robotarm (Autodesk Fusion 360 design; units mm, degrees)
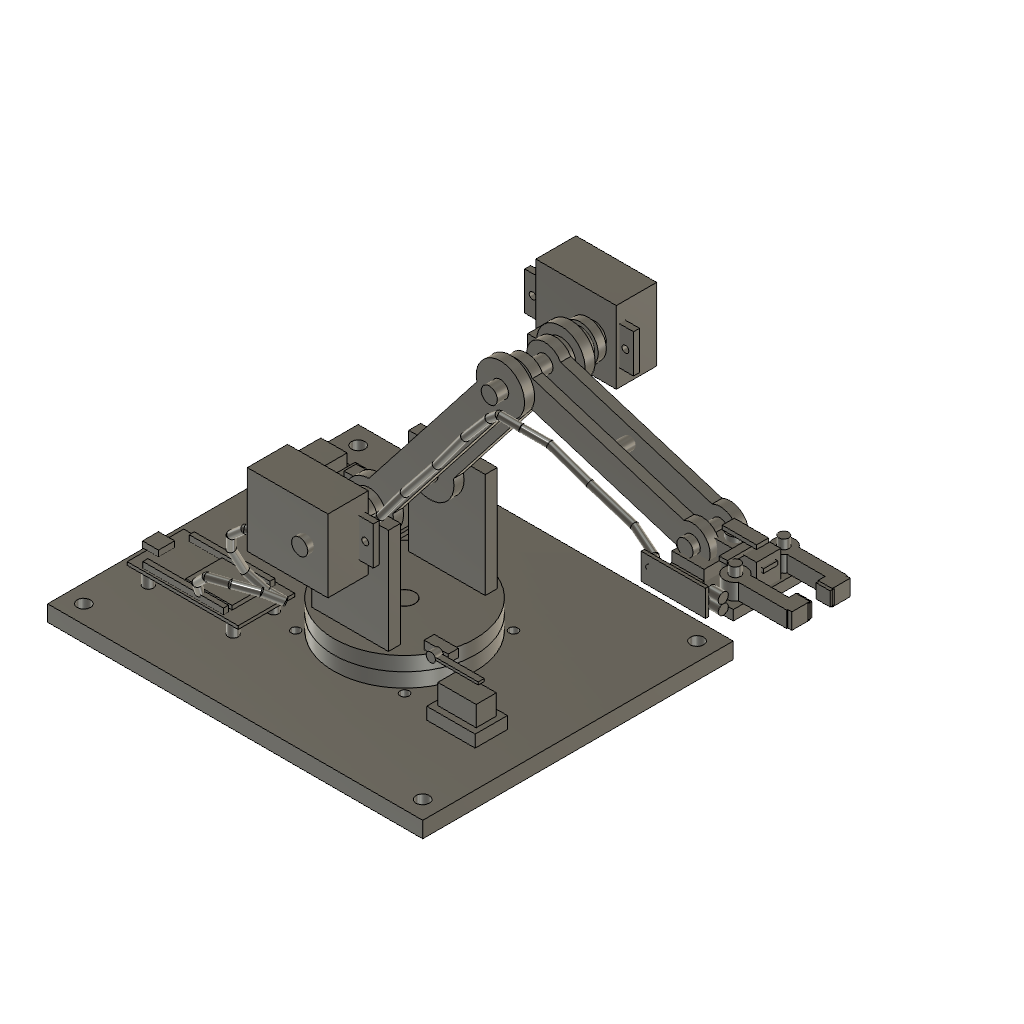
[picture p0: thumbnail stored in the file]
part number: 2026-11-24-23-50-12-086
part number: 2026-11-24-23-50-12-224
part number: 2026-11-24-23-50-12-256
part number: 2026-11-24-23-50-12-289
part number: 2026-11-24-23-50-12-323
part number: 2026-11-24-23-50-12-349
part number: 2026-11-24-23-50-12-379
part number: 2026-11-24-23-50-12-404
part number: 2026-11-24-23-50-12-427
part number: 2026-11-24-23-50-12-457
part number: 2026-11-24-23-50-12-485
part number: 2026-11-24-23-50-12-512
base_feature "Base Feature1" bodies "Base plate with corner and bearing holes", "Bearing lower race", "Turntable actuator envelope", "Turntable output shaft"
base_feature "Base Feature1" bodies "Turntable top plate", "Shoulder clevis cheek", "Shoulder clevis cheek (1)", "Servo housing envelope", "Mounting flange with M3 clearance", "Output boss", "Horn and shaft", "Shoulder servo mounting bridge"
base_feature "Base Feature1" bodies "Left shoulder link, 105 mm pivot spacing", "Right shoulder link, 105 mm pivot spacing", "Shoulder drive coupling", "Elbow servo mounting bridge", "Upper link cross spacer", "Elbow support pin", "Servo housing envelope", "Mounting flange with M3 clearance"
base_feature "Base Feature1" bodies "Left forearm link, 91 mm pivot spacing", "Right forearm link, 91 mm pivot spacing", "Forearm cross spacer", "Elbow drive coupling", "Wrist spacer and bolt pin", "Fixed wrist tool plate"
base_feature "Base Feature1" bodies "Tool carrier", "Micro servo package", "Servo output", "Servo horn", "Opposite jaw pivot", "Driven jaw pivot", "Drive link", "Synchronizer mounting envelope"
base_feature "Base Feature1" bodies "Jaw with pivot bore", "Grip pad"
base_feature "Base Feature1" bodies "Jaw with pivot bore", "Grip pad"
base_feature "Base Feature1" bodies "ESP32 board envelope", "Module shield", "Accessible USB connector", "GPIO header A", "GPIO header B", "PCB standoff", "PCB standoff (1)", "PCB standoff (2)"
base_feature "Base Feature1" bodies "Power board envelope", "External supply terminal block", "Servo power terminal block", "Power switch housing", "Switch actuator", "Power tray support"
base_feature "Base Feature1" bodies "Home switch mounting bracket", "Switch body", "Roller lever", "Lever roller"
base_feature "Base Feature1" bodies "Sensor mount", "IR module board envelope", "IR emitter", "IR receiver"
base_feature "Base Feature2" bodies "Wire retention clip"
base_feature "Base Feature2" bodies "Wire retention clip"
base_feature "Base Feature2" bodies "Wire retention clip"
base_feature "Base Feature2" bodies "Cable 1 - board to turntable"
base_feature "Base Feature3" bodies "Cable 2 - slack loop to shoulder servo"
base_feature "Base Feature3" bodies "Cable 3 - harness along upper arm"
base_feature "Base Feature3" bodies "Cable 4 - forearm to wrist IR sensor"
ground "Pin"
sketch "J1 Base yaw pivot reference" plane through (0, 0, 0) normal (0, 0, 1) x axis (1, 0, 0)
as_built_joint "As-built1" RotateMinimum -70 RotateMaximum 70
sketch "J2 Shoulder pitch pivot reference" plane through (0, 0, 0) normal (0, 0, 1) x axis (1, 0, 0)
as_built_joint "As-built2" RotateMinimum -30 RotateMaximum 35
sketch "J3 Elbow pitch pivot reference" plane through (0, 0, 0) normal (0, 0, 1) x axis (1, 0, 0)
as_built_joint "As-built3" RotateMinimum -35 RotateMaximum 40
sketch "J4 Driven jaw pivot reference" plane through (0, 0, 0) normal (0, 0, 1) x axis (1, 0, 0)
as_built_joint "As-built4" RotateMinimum -12 RotateMaximum 8
sketch "Follower jaw pivot pivot reference" plane through (0, 0, 0) normal (0, 0, 1) x axis (1, 0, 0)
as_built_joint "As-built5" RotateMinimum -8 RotateMaximum 12
as_built_joint "As-built6"
as_built_joint "As-built7"
as_built_joint "As-built8"
as_built_joint "As-built9"
as_built_joint "As-built10"
motion_link "MotionLink1" Value1 1 Value2 1
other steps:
create_component "CreateComponent1"
create_component "CreateComponent2"
create_component "CreateComponent3"
create_component "CreateComponent4"
create_component "CreateComponent5"
create_component "CreateComponent6"
create_component "CreateComponent7"
create_component "CreateComponent8"
create_component "CreateComponent9"
create_component "CreateComponent10"
create_component "CreateComponent11"
named bodies: "Base plate with corner and bearing holes", "Bearing lower race", "Turntable actuator envelope", "Turntable output shaft", "Turntable top plate", "Shoulder clevis cheek", "Shoulder clevis cheek (1)", "Servo housing envelope", "Mounting flange with M3 clearance", "Output boss", "Horn and shaft", "Shoulder servo mounting bridge", "Shoulder support pin", "Home flag carrier", "Left shoulder link, 105 mm pivot spacing", "Right shoulder link, 105 mm pivot spacing", "Shoulder drive coupling", "Elbow servo mounting bridge", "Upper link cross spacer", "Elbow support pin", "Left forearm link, 91 mm pivot spacing", "Right forearm link, 91 mm pivot spacing", "Forearm cross spacer", "Elbow drive coupling", "Wrist spacer and bolt pin", "Fixed wrist tool plate", "Tool carrier", "Micro servo package", "Servo output", "Servo horn", "Opposite jaw pivot", "Driven jaw pivot", "Drive link", "Synchronizer mounting envelope", "Jaw with pivot bore", "Grip pad", "ESP32 board envelope", "Module shield", "Accessible USB connector", "GPIO header A", "GPIO header B", "PCB standoff", "PCB standoff (1)", "PCB standoff (2)", "PCB standoff (3)", "Power board envelope", "External supply terminal block", "Servo power terminal block", "Power switch housing", "Switch actuator", "Power tray support", "Home switch mounting bracket", "Switch body", "Roller lever", "Lever roller", "Sensor mount", "IR module board envelope", "IR emitter", "IR receiver", "Wire retention clip"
